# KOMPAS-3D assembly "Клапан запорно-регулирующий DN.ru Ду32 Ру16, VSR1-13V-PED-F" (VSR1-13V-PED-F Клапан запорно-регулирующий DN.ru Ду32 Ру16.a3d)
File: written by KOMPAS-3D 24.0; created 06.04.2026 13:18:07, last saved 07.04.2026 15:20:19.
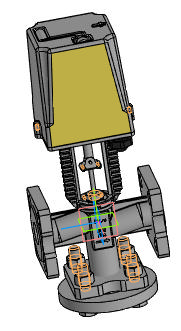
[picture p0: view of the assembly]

Document properties: Автор: R2D2; Полное имя файла: E:\Работа\Зайцев\Солянка\VSR1-13V-PED-F Клапан запорно-регулирующий DN.ru\DN32\исходные материалы\VSR1-13V-PED-F Клапан запорно-регулирующий DN.ru Ду32 Ру16.a3d

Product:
- Component [detail]: Фланец Ду32 Ру16  | qty 2  | pos. 1  | Масса: 1.157211; Автор: R2D2; source file: Фланец.m3d
- Component [detail]: Фланец Ду32 Ру16  | qty 1  | pos. 2  | Масса: 1.157211; Автор: R2D2; source file: Фланец.m3d
- Component [detail]: Корпус  | qty 1  | pos. 3  | Масса: 6.9; Автор: R2D2; source file: Корпус.m3d
- Component [detail]: Электропривод  | qty 1  | pos. 6  | Масса: 0.101125; Автор: R2D2; source file: Электропривод.m3d
- Component [standard]: Болт с шестигранной головкой ГОСТ Р ИСО 4014 - М16 x 65  | qty 4  | Материал: Не определено (density 1000 kg/m3); Масса: 0.1404; Раздел спецификации: Стандартные изделия; Рассекать на разрезах: no; additional columns: ГОСТ Р ИСО 4014-2013
- Component [standard]: Гайка М16-6H ГОСТ 5915-70  | qty 4  | Масса: 0.03761; Раздел спецификации: Стандартные изделия; Рассекать на разрезах: no; additional columns: М1,6-6H
- Part/product: Клапан запорно-регулирующий DN.ru Ду32 Ру16  | designation VSR1-13V-PED-F
    Масса: 9.2
    Раздел спецификации: Прочие изделия
    Примечание: D090-02889

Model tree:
1. Эскиз:1
2. Ось конической поверхности:19
3. Смещенная плоскость:19
4. ЛСК:19  (with: Плоскость XY, Плоскость ZX, Плоскость ZY, Ось X, Ось Y, Ось Z)
     Ось X. Y = -1; Ось Y. X = 1; Ось Z. Z = 1; Точка начала. Х = 35.3553; Точка начала. Y = -110; Точка начала. Z = 35.3553
5. Болтовое соединение
6. Массив по концентрической сетке:2  (with: Грань.Элемент выдавливания:1, Грань.Элемент вращения:1, Грань.Элемент выдавливания:2)  (labels: Грань.Элемент выдавливания:4.Экземпляр ( 1, 3 ))  (4 pattern instances)
     Шаг 2 = 360; Ориентация = 2; Расстояние = -2; Расстояние = -36

Expressions: VSR1-13V-PED-F; -L/2
Referenced files in E:\Работа\Зайцев\Солянка\VSR1-13V-PED-F Клапан запорно-регулирующий DN.ru\DN32\исходные материалы\: Фланец.m3d, Корпус.m3d, Электропривод.m3d
Referenced files in C:\Program Files\ASCON\KOMPAS-3D v24\Libs\PolynomLib\DATA\vault\Methods\Kompas\3D\: PLib_Bolt_1_ISO_1100.m3d, PLib_Nut_OST92_900.m3d
Referenced files in E:\Работа\Зайцев\Солянка\VSR1-13V-PED-F Клапан запорно-регулирующий DN.ru\DN20\исходные материалы\: Фланец.m3d
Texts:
  Болт с шестигранной головкой
  Крепежное изделие ГОСТ
  Программные изделия  и базы данных
  Edge1
  Edge2
  TKR3D
  Справочник стандартных изделий
  Фланец Ду32 Ру16 (1)
  Фланец Ду32 Ру16 (2)
  Фланец Ду32 Ру16 (3)
  Болт с шестигранной головкой ГОСТ Р ИСО 4014 - М16 x 65 (1)
  hole1
  hole2
  Гайка М16-6H ГОСТ 5915-70 (1)
  bcut1
  hcut1
  cut1
  Болт с шестигранной головкой ГОСТ Р ИСО 4014 - М16 x 65 (2)
  Гайка М16-6H ГОСТ 5915-70 (2)
  Болт с шестигранной головкой ГОСТ Р ИСО 4014 - М16 x 65 (3)
  Гайка М16-6H ГОСТ 5915-70 (3)
  Болт с шестигранной головкой ГОСТ Р ИСО 4014 - М16 x 65 (4)
  Гайка М16-6H ГОСТ 5915-70 (4)
  Плоскость XY.Начало координат
  Ось Z.Начало координат
  Плоскость ZY.Начало координат
  Плоскость ZX.Начало координат
  Ось Y.Начало координат
  Plane. Начало координат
